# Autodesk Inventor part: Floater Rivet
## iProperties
Shininess: 70.0
Angle Display Precision: 2
Document Length Units: 11269
Document Angle Units: 11279
Document Time Units: 11290
Document Mass Units: 11283
Document Length Units Precision: 3
Document Angle Units Precision: 2
Compacted: True
Created: 2001-09
Part Number: Floater Rivet
Document SubType Name: Modeling
Designer: rak
Description: Floater Rivet
Density: 0.0
Volumn: 0.0
Area: 0.0
PropertySet Name: Model Information
Control State: 0
Master: False
Checked Out: False
Author: rak
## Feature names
1. Extrusion1
2. Extrusion2
3. Extrusion3
4. Chamfer1
5. Extrusion4
6. Chamfer2
